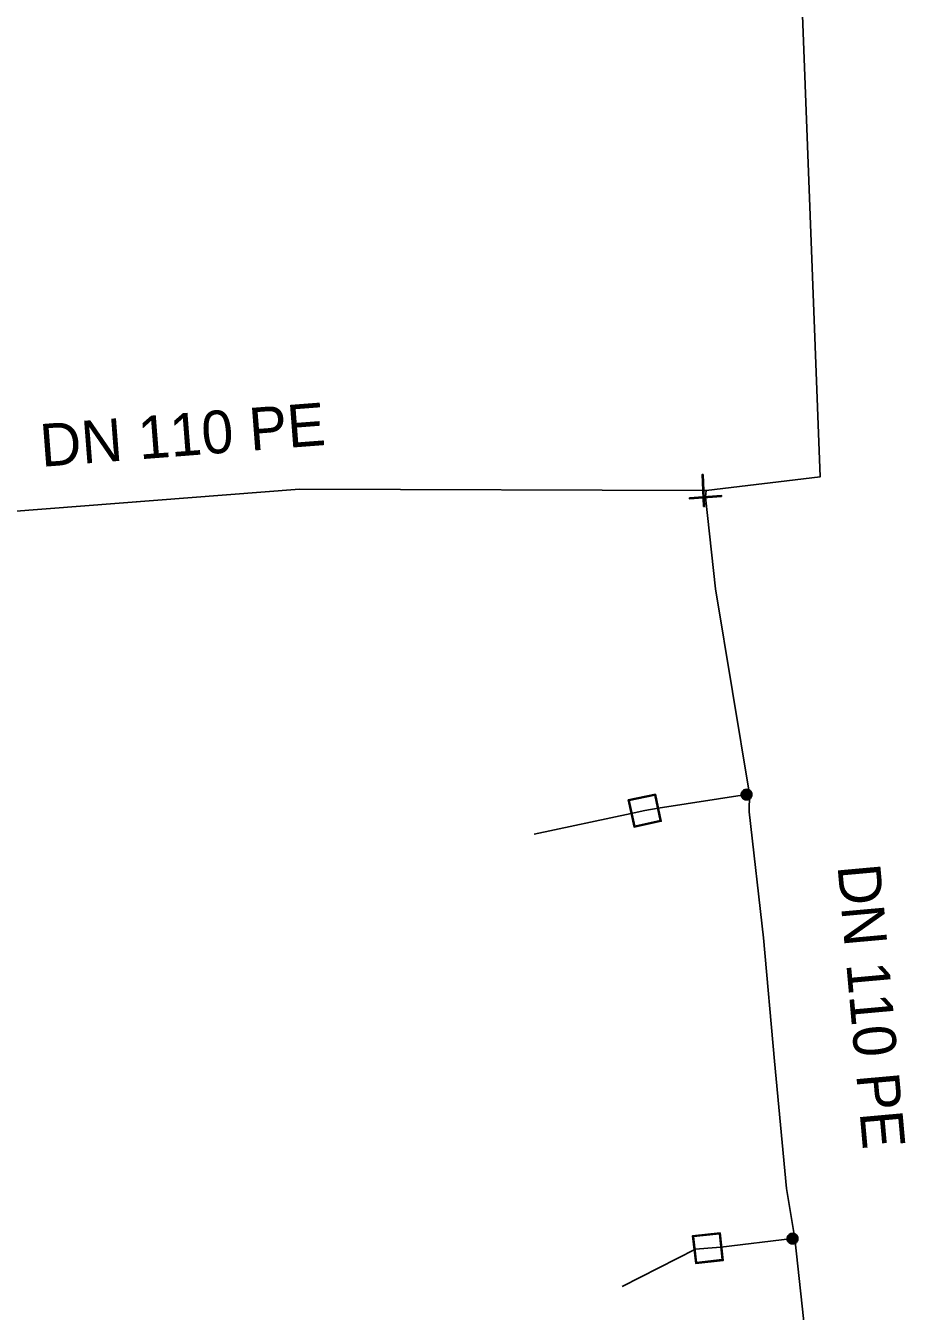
# Model space of a CAD drawing. Extents: x -832382 to -831581, y -1074670 to -1074251.
# Drawn here: x -831918.2 to -831877, y -1074447.1 to -1074386.9 of the extents above; entities that cross this region are included whole.
import ezdxf

# ---------------------------------------------------------------- set-up
doc = ezdxf.new("R2010")
doc.units = 0
for name, color, linetype in [('Přípojka vodovodu', 7, 'Continuous'), ('Přípojkový uzávěr', 7, 'Continuous'), ('Roz-řad', 7, 'Continuous'), ('Roz-řad-popis základní', 7, 'Continuous'), ('Řad-šoupě', 7, 'Continuous'), ('Šachta vodovodní', 7, 'Continuous')]:
    doc.layers.add(name, color=color, linetype=linetype)

msp = doc.modelspace()

# ---------------------------------------------------------------- linework, layer by layer
at = {"layer": 'Přípojka vodovodu'}
for points in [[(-831884.276, -1074422.86), (-831884.41, -1074422.88), (-831888.55, -1074423.51), (-831889.18, -1074423.63)], [(-831889.18, -1074423.63), (-831889.82, -1074423.76), (-831894.36, -1074424.73)], [(-831882.147, -1074443.657), (-831882.26, -1074443.67), (-831885.62, -1074444.07), (-831886.22, -1074444.115)], [(-831886.22, -1074444.115), (-831886.81, -1074444.16), (-831890.24, -1074445.91)]]:
    msp.add_lwpolyline(points, dxfattribs=at)
at = {"layer": 'Přípojkový uzávěr'}
for points in [[(-831884.41, -1074422.63), (-831884.347, -1074422.63), (-831884.287, -1074422.662), (-831884.228, -1074422.694), (-831884.194, -1074422.755), (-831884.16, -1074422.815), (-831884.16, -1074422.88), (-831884.16, -1074422.945), (-831884.193, -1074423.005), (-831884.226, -1074423.064), (-831884.285, -1074423.097), (-831884.345, -1074423.13), (-831884.41, -1074423.13), (-831884.475, -1074423.13), (-831884.535, -1074423.097), (-831884.594, -1074423.064), (-831884.627, -1074423.005), (-831884.66, -1074422.945), (-831884.66, -1074422.88), (-831884.66, -1074422.815), (-831884.626, -1074422.755), (-831884.593, -1074422.694), (-831884.533, -1074422.662), (-831884.473, -1074422.63), (-831884.41, -1074422.63)], [(-831884.41, -1074422.653), (-831884.467, -1074422.653), (-831884.522, -1074422.683), (-831884.576, -1074422.712), (-831884.606, -1074422.766), (-831884.637, -1074422.821), (-831884.637, -1074422.88), (-831884.637, -1074422.939), (-831884.607, -1074422.993), (-831884.577, -1074423.047), (-831884.523, -1074423.077), (-831884.469, -1074423.107), (-831884.41, -1074423.107), (-831884.351, -1074423.107), (-831884.297, -1074423.077), (-831884.243, -1074423.047), (-831884.213, -1074422.993), (-831884.183, -1074422.939), (-831884.183, -1074422.88), (-831884.183, -1074422.821), (-831884.214, -1074422.766), (-831884.245, -1074422.712), (-831884.299, -1074422.683), (-831884.353, -1074422.653), (-831884.41, -1074422.653)], [(-831884.41, -1074422.671), (-831884.357, -1074422.671), (-831884.307, -1074422.698), (-831884.257, -1074422.724), (-831884.229, -1074422.775), (-831884.201, -1074422.825), (-831884.201, -1074422.88), (-831884.201, -1074422.935), (-831884.228, -1074422.984), (-831884.255, -1074423.034), (-831884.306, -1074423.062), (-831884.356, -1074423.089), (-831884.41, -1074423.089), (-831884.464, -1074423.089), (-831884.514, -1074423.062), (-831884.565, -1074423.034), (-831884.592, -1074422.984), (-831884.619, -1074422.935), (-831884.619, -1074422.88), (-831884.619, -1074422.825), (-831884.591, -1074422.775), (-831884.563, -1074422.724), (-831884.513, -1074422.698), (-831884.463, -1074422.671), (-831884.41, -1074422.671)], [(-831884.41, -1074422.693), (-831884.489, -1074422.693), (-831884.543, -1074422.747), (-831884.598, -1074422.802), (-831884.598, -1074422.88), (-831884.598, -1074422.958), (-831884.543, -1074423.013), (-831884.488, -1074423.068), (-831884.41, -1074423.068), (-831884.332, -1074423.068), (-831884.277, -1074423.013), (-831884.223, -1074422.958), (-831884.223, -1074422.88), (-831884.223, -1074422.802), (-831884.277, -1074422.747), (-831884.332, -1074422.693), (-831884.41, -1074422.693)], [(-831884.41, -1074422.715), (-831884.342, -1074422.715), (-831884.294, -1074422.763), (-831884.246, -1074422.811), (-831884.246, -1074422.88), (-831884.246, -1074422.948), (-831884.294, -1074422.996), (-831884.342, -1074423.044), (-831884.41, -1074423.044), (-831884.479, -1074423.044), (-831884.527, -1074422.996), (-831884.575, -1074422.948), (-831884.575, -1074422.88), (-831884.575, -1074422.811), (-831884.527, -1074422.763), (-831884.479, -1074422.715), (-831884.41, -1074422.715)], [(-831884.41, -1074422.735), (-831884.471, -1074422.735), (-831884.513, -1074422.777), (-831884.555, -1074422.82), (-831884.555, -1074422.88), (-831884.555, -1074422.939), (-831884.513, -1074422.982), (-831884.471, -1074423.024), (-831884.41, -1074423.024), (-831884.351, -1074423.024), (-831884.308, -1074422.982), (-831884.266, -1074422.939), (-831884.266, -1074422.88), (-831884.266, -1074422.82), (-831884.308, -1074422.777), (-831884.35, -1074422.735), (-831884.41, -1074422.735)], [(-831884.41, -1074422.755), (-831884.358, -1074422.755), (-831884.321, -1074422.792), (-831884.285, -1074422.828), (-831884.285, -1074422.88), (-831884.285, -1074422.932), (-831884.322, -1074422.969), (-831884.358, -1074423.005), (-831884.41, -1074423.005), (-831884.462, -1074423.005), (-831884.498, -1074422.969), (-831884.535, -1074422.932), (-831884.535, -1074422.88), (-831884.535, -1074422.828), (-831884.499, -1074422.792), (-831884.462, -1074422.755), (-831884.41, -1074422.755)], [(-831884.41, -1074422.778), (-831884.452, -1074422.778), (-831884.482, -1074422.808), (-831884.512, -1074422.838), (-831884.512, -1074422.88), (-831884.512, -1074422.922), (-831884.482, -1074422.952), (-831884.452, -1074422.981), (-831884.41, -1074422.981), (-831884.368, -1074422.981), (-831884.338, -1074422.952), (-831884.309, -1074422.922), (-831884.309, -1074422.88), (-831884.309, -1074422.838), (-831884.338, -1074422.808), (-831884.368, -1074422.778), (-831884.41, -1074422.778)], [(-831884.41, -1074422.796), (-831884.375, -1074422.796), (-831884.351, -1074422.82), (-831884.326, -1074422.845), (-831884.326, -1074422.88), (-831884.326, -1074422.915), (-831884.351, -1074422.939), (-831884.375, -1074422.964), (-831884.41, -1074422.964), (-831884.445, -1074422.964), (-831884.47, -1074422.939), (-831884.494, -1074422.915), (-831884.494, -1074422.88), (-831884.494, -1074422.845), (-831884.47, -1074422.82), (-831884.445, -1074422.796), (-831884.41, -1074422.796)], [(-831884.41, -1074422.818), (-831884.436, -1074422.818), (-831884.454, -1074422.836), (-831884.473, -1074422.854), (-831884.473, -1074422.88), (-831884.473, -1074422.906), (-831884.454, -1074422.924), (-831884.436, -1074422.943), (-831884.41, -1074422.943), (-831884.384, -1074422.943), (-831884.366, -1074422.924), (-831884.348, -1074422.906), (-831884.348, -1074422.88), (-831884.348, -1074422.854), (-831884.366, -1074422.836), (-831884.384, -1074422.818), (-831884.41, -1074422.818)], [(-831884.41, -1074422.841), (-831884.394, -1074422.841), (-831884.382, -1074422.852), (-831884.371, -1074422.863), (-831884.371, -1074422.88), (-831884.371, -1074422.896), (-831884.382, -1074422.908), (-831884.394, -1074422.919), (-831884.41, -1074422.919), (-831884.426, -1074422.919), (-831884.438, -1074422.908), (-831884.449, -1074422.896), (-831884.449, -1074422.88), (-831884.449, -1074422.863), (-831884.438, -1074422.852), (-831884.426, -1074422.841), (-831884.41, -1074422.841)], [(-831884.41, -1074422.857), (-831884.42, -1074422.857), (-831884.427, -1074422.863), (-831884.434, -1074422.87), (-831884.434, -1074422.88), (-831884.434, -1074422.89), (-831884.427, -1074422.897), (-831884.42, -1074422.903), (-831884.41, -1074422.903), (-831884.4, -1074422.903), (-831884.394, -1074422.897), (-831884.387, -1074422.89), (-831884.387, -1074422.88), (-831884.387, -1074422.87), (-831884.394, -1074422.863), (-831884.4, -1074422.857), (-831884.41, -1074422.857)], [(-831882.26, -1074443.42), (-831882.197, -1074443.42), (-831882.137, -1074443.452), (-831882.078, -1074443.484), (-831882.044, -1074443.545), (-831882.01, -1074443.605), (-831882.01, -1074443.67), (-831882.01, -1074443.735), (-831882.043, -1074443.795), (-831882.076, -1074443.854), (-831882.135, -1074443.887), (-831882.195, -1074443.92), (-831882.26, -1074443.92), (-831882.325, -1074443.92), (-831882.385, -1074443.887), (-831882.444, -1074443.854), (-831882.477, -1074443.795), (-831882.51, -1074443.735), (-831882.51, -1074443.67), (-831882.51, -1074443.605), (-831882.476, -1074443.545), (-831882.443, -1074443.484), (-831882.383, -1074443.452), (-831882.323, -1074443.42), (-831882.26, -1074443.42)], [(-831882.26, -1074443.443), (-831882.317, -1074443.443), (-831882.372, -1074443.473), (-831882.426, -1074443.502), (-831882.456, -1074443.556), (-831882.487, -1074443.611), (-831882.487, -1074443.67), (-831882.487, -1074443.729), (-831882.457, -1074443.783), (-831882.427, -1074443.837), (-831882.373, -1074443.867), (-831882.319, -1074443.897), (-831882.26, -1074443.897), (-831882.201, -1074443.897), (-831882.147, -1074443.867), (-831882.093, -1074443.837), (-831882.063, -1074443.783), (-831882.033, -1074443.729), (-831882.033, -1074443.67), (-831882.033, -1074443.611), (-831882.064, -1074443.556), (-831882.095, -1074443.502), (-831882.149, -1074443.473), (-831882.203, -1074443.443), (-831882.26, -1074443.443)], [(-831882.26, -1074443.461), (-831882.207, -1074443.461), (-831882.157, -1074443.488), (-831882.107, -1074443.514), (-831882.079, -1074443.565), (-831882.051, -1074443.615), (-831882.051, -1074443.67), (-831882.051, -1074443.725), (-831882.078, -1074443.774), (-831882.105, -1074443.824), (-831882.156, -1074443.852), (-831882.206, -1074443.879), (-831882.26, -1074443.879), (-831882.314, -1074443.879), (-831882.364, -1074443.852), (-831882.415, -1074443.824), (-831882.442, -1074443.774), (-831882.469, -1074443.725), (-831882.469, -1074443.67), (-831882.469, -1074443.615), (-831882.441, -1074443.565), (-831882.413, -1074443.514), (-831882.363, -1074443.488), (-831882.313, -1074443.461), (-831882.26, -1074443.461)], [(-831882.26, -1074443.483), (-831882.339, -1074443.483), (-831882.393, -1074443.537), (-831882.448, -1074443.592), (-831882.448, -1074443.67), (-831882.448, -1074443.748), (-831882.393, -1074443.803), (-831882.338, -1074443.858), (-831882.26, -1074443.858), (-831882.182, -1074443.858), (-831882.127, -1074443.803), (-831882.073, -1074443.748), (-831882.073, -1074443.67), (-831882.073, -1074443.592), (-831882.127, -1074443.537), (-831882.182, -1074443.483), (-831882.26, -1074443.483)], [(-831882.26, -1074443.505), (-831882.192, -1074443.505), (-831882.144, -1074443.553), (-831882.096, -1074443.601), (-831882.096, -1074443.67), (-831882.096, -1074443.738), (-831882.144, -1074443.786), (-831882.192, -1074443.834), (-831882.26, -1074443.834), (-831882.329, -1074443.834), (-831882.377, -1074443.786), (-831882.425, -1074443.738), (-831882.425, -1074443.67), (-831882.425, -1074443.601), (-831882.377, -1074443.553), (-831882.329, -1074443.505), (-831882.26, -1074443.505)], [(-831882.26, -1074443.525), (-831882.321, -1074443.525), (-831882.363, -1074443.567), (-831882.405, -1074443.61), (-831882.405, -1074443.67), (-831882.405, -1074443.729), (-831882.363, -1074443.772), (-831882.321, -1074443.814), (-831882.26, -1074443.814), (-831882.201, -1074443.814), (-831882.158, -1074443.772), (-831882.116, -1074443.729), (-831882.116, -1074443.67), (-831882.116, -1074443.61), (-831882.158, -1074443.567), (-831882.2, -1074443.525), (-831882.26, -1074443.525)], [(-831882.26, -1074443.545), (-831882.208, -1074443.545), (-831882.171, -1074443.582), (-831882.135, -1074443.618), (-831882.135, -1074443.67), (-831882.135, -1074443.722), (-831882.172, -1074443.759), (-831882.208, -1074443.795), (-831882.26, -1074443.795), (-831882.312, -1074443.795), (-831882.348, -1074443.759), (-831882.385, -1074443.722), (-831882.385, -1074443.67), (-831882.385, -1074443.618), (-831882.349, -1074443.582), (-831882.312, -1074443.545), (-831882.26, -1074443.545)], [(-831882.26, -1074443.568), (-831882.302, -1074443.568), (-831882.332, -1074443.598), (-831882.362, -1074443.628), (-831882.362, -1074443.67), (-831882.362, -1074443.712), (-831882.332, -1074443.742), (-831882.302, -1074443.771), (-831882.26, -1074443.771), (-831882.218, -1074443.771), (-831882.188, -1074443.742), (-831882.159, -1074443.712), (-831882.159, -1074443.67), (-831882.159, -1074443.628), (-831882.188, -1074443.598), (-831882.218, -1074443.568), (-831882.26, -1074443.568)], [(-831882.26, -1074443.586), (-831882.225, -1074443.586), (-831882.201, -1074443.61), (-831882.176, -1074443.635), (-831882.176, -1074443.67), (-831882.176, -1074443.705), (-831882.201, -1074443.729), (-831882.225, -1074443.754), (-831882.26, -1074443.754), (-831882.295, -1074443.754), (-831882.32, -1074443.729), (-831882.344, -1074443.705), (-831882.344, -1074443.67), (-831882.344, -1074443.635), (-831882.32, -1074443.61), (-831882.295, -1074443.586), (-831882.26, -1074443.586)], [(-831882.26, -1074443.608), (-831882.286, -1074443.608), (-831882.304, -1074443.626), (-831882.323, -1074443.644), (-831882.323, -1074443.67), (-831882.323, -1074443.696), (-831882.304, -1074443.714), (-831882.286, -1074443.733), (-831882.26, -1074443.733), (-831882.234, -1074443.733), (-831882.216, -1074443.714), (-831882.198, -1074443.696), (-831882.198, -1074443.67), (-831882.198, -1074443.644), (-831882.216, -1074443.626), (-831882.234, -1074443.608), (-831882.26, -1074443.608)], [(-831882.26, -1074443.631), (-831882.244, -1074443.631), (-831882.232, -1074443.642), (-831882.221, -1074443.653), (-831882.221, -1074443.67), (-831882.221, -1074443.686), (-831882.232, -1074443.698), (-831882.244, -1074443.709), (-831882.26, -1074443.709), (-831882.276, -1074443.709), (-831882.288, -1074443.698), (-831882.299, -1074443.686), (-831882.299, -1074443.67), (-831882.299, -1074443.653), (-831882.288, -1074443.642), (-831882.276, -1074443.631), (-831882.26, -1074443.631)], [(-831882.26, -1074443.647), (-831882.27, -1074443.647), (-831882.277, -1074443.653), (-831882.284, -1074443.66), (-831882.284, -1074443.67), (-831882.284, -1074443.68), (-831882.277, -1074443.687), (-831882.27, -1074443.693), (-831882.26, -1074443.693), (-831882.25, -1074443.693), (-831882.244, -1074443.687), (-831882.237, -1074443.68), (-831882.237, -1074443.67), (-831882.237, -1074443.66), (-831882.244, -1074443.653), (-831882.25, -1074443.647), (-831882.26, -1074443.647)]]:
    msp.add_open_spline(points, degree=3, dxfattribs=at)
at = {"layer": 'Roz-řad'}
for q in [(-831886.44, -1074408.64), (-831886.33, -1074408.96)]:
    msp.add_line((-831886.3, -1074408.64), q, dxfattribs=at)
for points in [[(-831886.3, -1074408.64), (-831880.97, -1074408.01), (-831882.036, -1074380.258), (-831888.259, -1074367.098), (-831888.249, -1074366.757), (-831887.64, -1074355.49), (-831887.73, -1074344.47), (-831887.76, -1074343.52), (-831889.32, -1074321.29)], [(-831886.44, -1074408.64), (-831905.34, -1074408.59), (-831920.63, -1074409.77), (-831929.6, -1074411.16), (-831944.61, -1074414.5), (-831953.4, -1074417.02), (-831952.245, -1074422.863), (-831952.065, -1074424.626), (-831951.81, -1074427.06), (-831950.24, -1074438.21), (-831949.124, -1074445.161), (-831946.578, -1074461.011), (-831946.13, -1074461.88)], [(-831886.33, -1074408.96), (-831885.87, -1074413.25), (-831884.276, -1074422.86), (-831884.29, -1074423.69), (-831883.62, -1074429.58), (-831883.1, -1074435.36), (-831882.54, -1074441.32), (-831882.147, -1074443.657), (-831881.13, -1074453.16), (-831880.618, -1074458.746), (-831880.65, -1074459.53)]]:
    msp.add_lwpolyline(points, dxfattribs=at)
at = {"layer": 'Řad-šoupě'}
for points in [[(-831886.43, -1074409.4), (-831886.496, -1074407.902), (-831886.45, -1074407.9), (-831886.384, -1074409.398), (-831886.43, -1074409.4)], [(-831885.58, -1074408.93), (-831887.076, -1074409.037), (-831887.08, -1074408.99), (-831885.584, -1074408.883), (-831885.58, -1074408.93)]]:
    msp.add_lwpolyline(points, dxfattribs=at)
at = {"layer": 'Šachta vodovodní'}
for points in [[(-831888.678, -1074422.859), (-831888.409, -1074424.131), (-831889.681, -1074424.4), (-831889.95, -1074423.129), (-831888.678, -1074422.859)], [(-831889.902, -1074423.16), (-831889.65, -1074424.352), (-831888.457, -1074424.1), (-831888.71, -1074422.908), (-831889.902, -1074423.16)], [(-831885.644, -1074443.394), (-831885.503, -1074444.686), (-831886.795, -1074444.827), (-831886.936, -1074443.534), (-831885.644, -1074443.394)], [(-831886.892, -1074443.57), (-831886.759, -1074444.782), (-831885.548, -1074444.65), (-831885.68, -1074443.438), (-831886.892, -1074443.57)]]:
    msp.add_lwpolyline(points, dxfattribs=at)

# ---------------------------------------------------------------- texts
at = {"layer": 'Roz-řad-popis základní'}
for rotation, p in [(4.41304, (-831917.409, -1074407.541)), (275.14081, (-831880.159, -1074426.212))]:
    msp.add_text('DN 110 PE', height=2, rotation=rotation, dxfattribs=at).set_placement(p)

doc.saveas('drawing.dxf')
